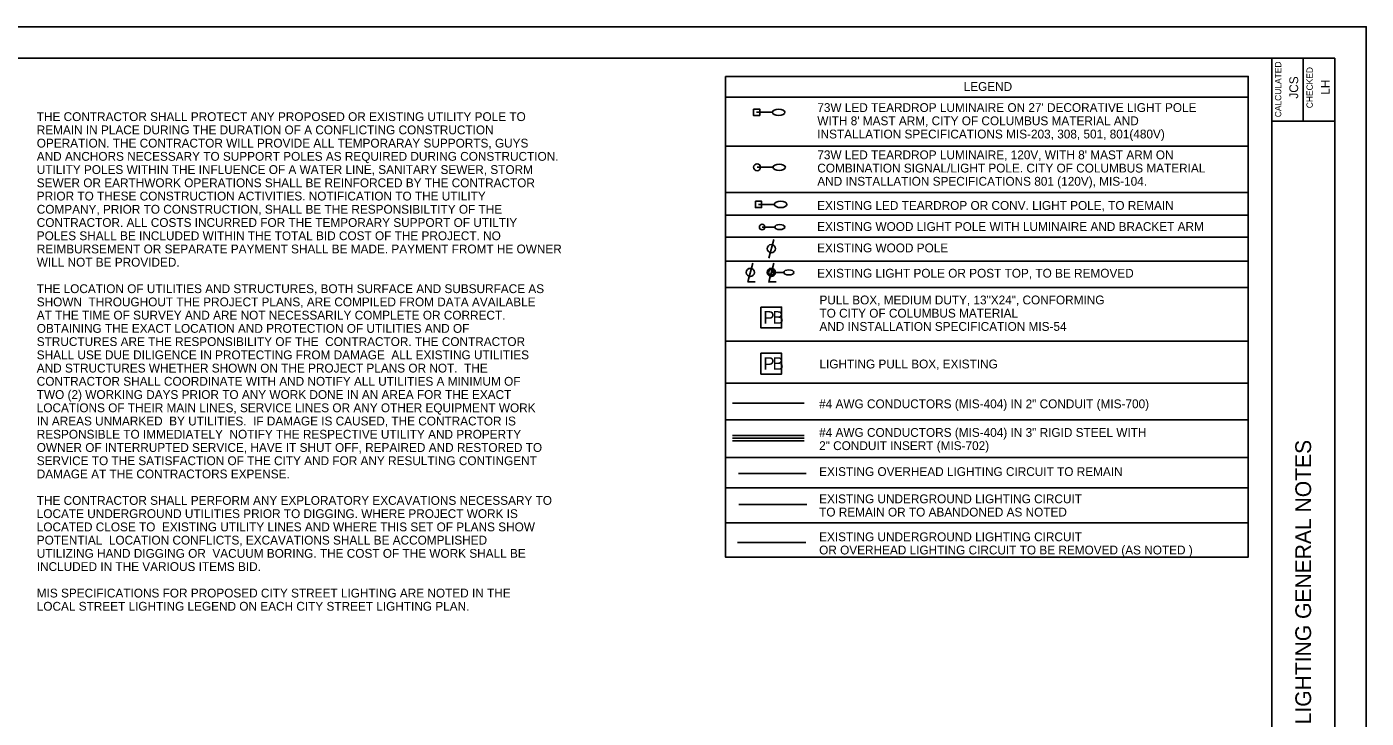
# Model space of a CAD drawing. Extents: x 0 to 34, y 0 to 22.
# Drawn here: x 12.74 to 34, y 11.03 to 22 of the extents above; entities that cross this region are included whole.
import ezdxf

# ---------------------------------------------------------------- set-up
doc = ezdxf.new("R2010")
doc.units = 0
for name, color, linetype in [('LT_P_Circuit3', 7, 'Continuous'), ('LT_P_Conduit', 7, 'Continuous'), ('LT_P_Control_Center', 7, 'Continuous'), ('LT_P_Luminaires', 7, 'Continuous'), ('LT_P_PullBox', 7, 'Continuous'), ('LT_P_Text', 7, 'Continuous'), ('LT_X_Control_Center', 7, 'Continuous'), ('LT_X_Luminaires', 7, 'Continuous'), ('LT_X_PullBox', 7, 'Continuous'), ('SH_Border', 7, 'Continuous'), ('SH_Cut_Line', 7, 'Continuous'), ('SH_Data', 7, 'Continuous')]:
    doc.layers.add(name, color=color, linetype=linetype)

msp = doc.modelspace()

# ---------------------------------------------------------------- linework, layer by layer
at = {"layer": 'LT_P_Circuit3'}
for points in [[(24.266, 18.25), (24.187, 17.951), (24.305, 17.951)], [(24.598, 18.25), (24.519, 17.951), (24.637, 17.951)]]:
    msp.add_lwpolyline(points, dxfattribs=at)
for centre in [(24.226, 18.102), (24.558, 18.102)]:
    msp.add_circle(centre, 0.065, dxfattribs=at)
at = {"layer": 'LT_P_Conduit'}
for p, q in [((24.356, 19.181), (24.606, 19.181)), ((24.413, 18.822), (24.613, 18.822)), ((24.558, 18.102), (24.758, 18.102))]:
    msp.add_line(p, q, dxfattribs=at)
msp.add_lwpolyline([(24.306, 19.231), (24.406, 19.231), (24.406, 19.131), (24.306, 19.131)], close=True, dxfattribs=at)
for centre in [(24.413, 18.822), (24.558, 18.102)]:
    msp.add_circle(centre, 0.044, dxfattribs=at)
for centre, major_axis in [((24.706, 19.181), (0.1, 0)), ((24.693, 18.822), (0.08, 0)), ((24.838, 18.102), (0.08, 0))]:
    msp.add_ellipse(centre, major_axis=major_axis, ratio=0.5, dxfattribs=at)
at = {"layer": 'LT_P_Control_Center'}
for p, q in [((24.558, 17.386), (24.558, 17.386)), ((24.558, 16.655), (24.558, 16.655))]:
    msp.add_line(p, q, dxfattribs=at)
for points in [[(24.393, 17.551), (24.723, 17.551), (24.723, 17.221), (24.393, 17.221)], [(24.393, 16.82), (24.723, 16.82), (24.723, 16.49), (24.393, 16.49)]]:
    msp.add_lwpolyline(points, close=True, dxfattribs=at)
at = {"layer": 'LT_P_Luminaires'}
for p, q in [((24.326, 20.643), (24.576, 20.643)), ((24.334, 19.771), (24.584, 19.771)), ((24.598, 18.627), (24.519, 18.327))]:
    msp.add_line(p, q, dxfattribs=at)
msp.add_lwpolyline([(24.276, 20.693), (24.376, 20.693), (24.376, 20.593), (24.276, 20.593)], close=True, dxfattribs=at)
for centre, radius in [((24.334, 19.771), 0.055), ((24.558, 18.479), 0.065)]:
    msp.add_circle(centre, radius, dxfattribs=at)
for centre in [(24.676, 20.643), (24.684, 19.771)]:
    msp.add_ellipse(centre, major_axis=(0.1, 0), ratio=0.5, dxfattribs=at)
at = {"layer": 'LT_P_Text'}
for p, q in [((23.83, 20.884), (32.129, 20.884)), ((23.83, 20.107), (32.129, 20.107)), ((23.83, 19.373), (32.129, 19.373)), ((23.83, 19.011), (32.129, 19.011)), ((23.83, 18.663), (32.129, 18.663)), ((23.83, 18.28), (32.129, 18.28)), ((23.83, 17.861), (32.129, 17.861)), ((23.83, 17.011), (32.129, 17.011)), ((23.83, 16.343), (32.129, 16.343)), ((23.83, 15.763), (32.129, 15.763)), ((23.83, 15.165), (32.129, 15.165)), ((23.83, 14.683), (32.129, 14.683)), ((23.83, 14.126), (32.129, 14.126))]:
    msp.add_line(p, q, dxfattribs=at)
msp.add_lwpolyline([(23.83, 21.213), (32.129, 21.213), (32.129, 13.584), (23.83, 13.584)], close=True, dxfattribs=at)
at = {"layer": 'LT_X_Control_Center'}
for p, q in [((23.944, 16.025), (25.08, 16.025)), ((23.944, 15.515), (25.08, 15.515)), ((23.944, 15.472), (25.08, 15.472)), ((23.944, 15.43), (25.08, 15.43))]:
    msp.add_line(p, q, dxfattribs=at)
at = {"layer": 'LT_X_Luminaires'}
for p, q in [((24.037, 14.91), (25.11, 14.91)), ((24.043, 14.421), (25.125, 14.421))]:
    msp.add_line(p, q, dxfattribs=at)
at = {"layer": 'LT_X_PullBox'}
msp.add_line((24.023, 13.814), (25.109, 13.814), dxfattribs=at)
at = {"layer": 'SH_Border'}
for p, q in [((32.5, 0.5), (32.5, 21.5)), ((33, 21.5), (33, 20.5)), ((32.5, 20.5), (33.5, 20.5))]:
    msp.add_line(p, q, dxfattribs=at)
msp.add_lwpolyline([(2, 21.5), (33.5, 21.5), (33.5, 0.5), (2, 0.5)], close=True, dxfattribs=at)
at = {"layer": 'SH_Cut_Line'}
msp.add_lwpolyline([(0, 0), (34, 0), (34, 22), (0, 22)], close=True, dxfattribs=at)

# ---------------------------------------------------------------- texts
at = {"layer": 'LT_P_Control_Center'}
for s, p in [('P', (24.431, 17.288)), ('B', (24.578, 17.288)), ('P', (24.431, 16.557)), ('B', (24.578, 16.557))]:
    msp.add_text(s, height=0.2, dxfattribs=at).set_placement(p)
at = {"layer": 'LT_P_PullBox'}
for s, p in [("73W LED TEARDROP LUMINAIRE ON 27' DECORATIVE LIGHT POLE ", (25.289, 20.648)), ("WITH 8' MAST ARM, CITY OF COLUMBUS MATERIAL AND ", (25.289, 20.438)), ('INSTALLATION SPECIFICATIONS MIS-203, 308, 501, 801(480V)', (25.289, 20.228)), ("73W LED TEARDROP LUMINAIRE, 120V, WITH 8' MAST ARM ON ", (25.289, 19.898)), ('COMBINATION SIGNAL/LIGHT POLE. CITY OF COLUMBUS MATERIAL ', (25.289, 19.688)), ('AND INSTALLATION SPECIFICATIONS 801 (120V), MIS-104.', (25.289, 19.478)), ('EXISTING LED TEARDROP OR CONV. LIGHT POLE, TO REMAIN', (25.286, 19.095)), ('EXISTING WOOD LIGHT POLE WITH LUMINAIRE AND BRACKET ARM', (25.286, 18.76)), ('EXISTING WOOD POLE', (25.286, 18.421)), ('EXISTING LIGHT POLE OR POST TOP, TO BE REMOVED', (25.286, 18.019)), ('PULL BOX, MEDIUM DUTY, 13"X24", CONFORMING ', (25.323, 17.595)), ('TO CITY OF COLUMBUS MATERIAL ', (25.323, 17.385)), ('AND INSTALLATION SPECIFICATION MIS-54', (25.323, 17.175)), ('LIGHTING PULL BOX, EXISTING', (25.323, 16.579)), ('#4 AWG CONDUCTORS (MIS-404) IN 2" CONDUIT (MIS-700)', (25.318, 15.947)), ('#4 AWG CONDUCTORS (MIS-404) IN 3" RIGID STEEL WITH ', (25.318, 15.493)), ('2" CONDUIT INSERT (MIS-702)', (25.318, 15.283)), ('EXISTING OVERHEAD LIGHTING CIRCUIT TO REMAIN', (25.318, 14.871)), ('EXISTING UNDERGROUND LIGHTING CIRCUIT ', (25.318, 14.439)), ('TO REMAIN OR TO ABANDONED AS NOTED', (25.318, 14.229)), ('EXISTING UNDERGROUND LIGHTING CIRCUIT ', (25.318, 13.837)), ('OR OVERHEAD LIGHTING CIRCUIT TO BE REMOVED (AS NOTED )', (25.318, 13.627))]:
    msp.add_text(s, height=0.14, rotation=360, dxfattribs=at).set_placement(p)
at = {"layer": 'LT_P_Text'}
msp.add_text('LEGEND', height=0.14, dxfattribs=at).set_placement((27.612, 20.982))
for s, p in [('THE CONTRACTOR SHALL PROTECT ANY PROPOSED OR EXISTING UTILITY POLE TO ', (12.902, 20.504)), ('REMAIN IN PLACE DURING THE DURATION OF A CONFLICTING CONSTRUCTION ', (12.902, 20.294)), ('OPERATION. THE CONTRACTOR WILL PROVIDE ALL TEMPORARAY SUPPORTS, GUYS ', (12.902, 20.084)), ('AND ANCHORS NECESSARY TO SUPPORT POLES AS REQUIRED DURING CONSTRUCTION. ', (12.902, 19.874)), ('UTILITY POLES WITHIN THE INFLUENCE OF A WATER LINE, SANITARY SEWER, STORM ', (12.902, 19.664)), ('SEWER OR EARTHWORK OPERATIONS SHALL BE REINFORCED BY THE CONTRACTOR ', (12.902, 19.454)), ('PRIOR TO THESE CONSTRUCTION ACTIVITIES. NOTIFICATION TO THE UTILITY ', (12.902, 19.244)), ('COMPANY, PRIOR TO CONSTRUCTION, SHALL BE THE RESPONSIBILTITY OF THE ', (12.902, 19.034)), ('CONTRACTOR. ALL COSTS INCURRED FOR THE TEMPORARY SUPPORT OF UTILTIY ', (12.902, 18.824)), ('POLES SHALL BE INCLUDED WITHIN THE TOTAL BID COST OF THE PROJECT. NO ', (12.902, 18.614)), ('REIMBURSEMENT OR SEPARATE PAYMENT SHALL BE MADE. PAYMENT FROMT HE OWNER ', (12.902, 18.404)), ('WILL NOT BE PROVIDED. ', (12.902, 18.194)), ('THE LOCATION OF UTILITIES AND STRUCTURES, BOTH SURFACE AND SUBSURFACE AS ', (12.902, 17.774)), ('SHOWN  THROUGHOUT THE PROJECT PLANS, ARE COMPILED FROM DATA AVAILABLE ', (12.902, 17.564)), ('AT THE TIME OF SURVEY AND ARE NOT NECESSARILY COMPLETE OR CORRECT.  ', (12.902, 17.354)), ('OBTAINING THE EXACT LOCATION AND PROTECTION OF UTILITIES AND OF ', (12.902, 17.144)), ('STRUCTURES ARE THE RESPONSIBILITY OF THE  CONTRACTOR. THE CONTRACTOR ', (12.902, 16.934)), ('SHALL USE DUE DILIGENCE IN PROTECTING FROM DAMAGE  ALL EXISTING UTILITIES ', (12.902, 16.724)), ('AND STRUCTURES WHETHER SHOWN ON THE PROJECT PLANS OR NOT.  THE ', (12.902, 16.514)), ('CONTRACTOR SHALL COORDINATE WITH AND NOTIFY ALL UTILITIES A MINIMUM OF ', (12.902, 16.304)), ('TWO (2) WORKING DAYS PRIOR TO ANY WORK DONE IN AN AREA FOR THE EXACT ', (12.902, 16.094)), ('LOCATIONS OF THEIR MAIN LINES, SERVICE LINES OR ANY OTHER EQUIPMENT WORK ', (12.902, 15.884)), ('IN AREAS UNMARKED  BY UTILITIES.  IF DAMAGE IS CAUSED, THE CONTRACTOR IS ', (12.902, 15.674)), ('RESPONSIBLE TO IMMEDIATELY  NOTIFY THE RESPECTIVE UTILITY AND PROPERTY ', (12.902, 15.464)), ('OWNER OF INTERRUPTED SERVICE, HAVE IT SHUT OFF, REPAIRED AND RESTORED TO ', (12.902, 15.254)), ('SERVICE TO THE SATISFACTION OF THE CITY AND FOR ANY RESULTING CONTINGENT ', (12.902, 15.044)), ('DAMAGE AT THE CONTRACTORS EXPENSE.', (12.902, 14.834)), ('THE CONTRACTOR SHALL PERFORM ANY EXPLORATORY EXCAVATIONS NECESSARY TO ', (12.902, 14.414)), ('LOCATE UNDERGROUND UTILITIES PRIOR TO DIGGING. WHERE PROJECT WORK IS ', (12.902, 14.204)), ('LOCATED CLOSE TO  EXISTING UTILITY LINES AND WHERE THIS SET OF PLANS SHOW ', (12.902, 13.994)), ('POTENTIAL  LOCATION CONFLICTS, EXCAVATIONS SHALL BE ACCOMPLISHED ', (12.902, 13.784)), ('UTILIZING HAND DIGGING OR  VACUUM BORING. THE COST OF THE WORK SHALL BE ', (12.902, 13.574)), ('INCLUDED IN THE VARIOUS ITEMS BID.', (12.902, 13.364)), ('MIS SPECIFICATIONS FOR PROPOSED CITY STREET LIGHTING ARE NOTED IN THE ', (12.902, 12.944)), ('LOCAL STREET LIGHTING LEGEND ON EACH CITY STREET LIGHTING PLAN. ', (12.902, 12.734))]:
    msp.add_text(s, height=0.14, rotation=360, dxfattribs=at).set_placement(p)
at = {"layer": 'SH_Data'}
for s, height, p in [('CALCULATED', 0.1, (32.652, 20.565)), ('CHECKED', 0.1, (33.152, 20.708)), ('JCS', 0.14, (32.92, 20.86)), ('LH', 0.14, (33.42, 20.922)), (' CITY OF COLUMBUS - LIGHTING GENERAL NOTES  ', 0.25, (33.125, 7.235))]:
    msp.add_text(s, height=height, rotation=90, dxfattribs=at).set_placement(p)

doc.saveas('drawing.dxf')
